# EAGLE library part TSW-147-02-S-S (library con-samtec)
THROUGH-HOLE .025" SQ POST HEADER Source: Samtec TSW.pdf
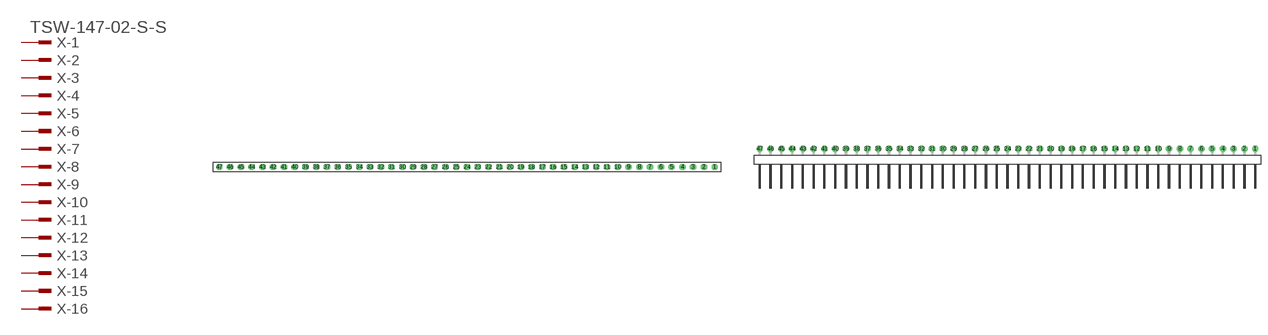
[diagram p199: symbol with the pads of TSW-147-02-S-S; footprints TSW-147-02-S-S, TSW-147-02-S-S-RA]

Designator prefix X; gates -1=MPINV -2=MPIN -3=MPIN -4=MPIN -5=MPIN -6=MPIN -7=MPIN -8=MPIN -9=MPIN -10=MPIN -11=MPIN -12=MPIN -13=MPIN -14=MPIN -15=MPIN -16=MPIN -17=MPIN -18=MPIN -19=MPIN -20=MPIN -21=MPIN -22=MPIN -23=MPIN -24=MPIN -25=MPIN -26=MPIN -27=MPIN -28=MPIN -29=MPIN -30=MPIN -31=MPIN -32=MPIN -33=MPIN -34=MPIN -35=MPIN -36=MPIN -37=MPIN -38=MPIN -39=MPIN -40=MPIN -41=MPIN -42=MPIN -43=MPIN -44=MPIN -45=MPIN -46=MPIN -47=MPIN

## TSW-147-02-S-S (OC_FARNELL: unknown; OC_NEWARK: unknown)  [TSW-147-02-S-S]
1  -1:1  pas
2  -2:1  pas
3  -3:1  pas
4  -4:1  pas
5  -5:1  pas
6  -6:1  pas
7  -7:1  pas
8  -8:1  pas
9  -9:1  pas
10  -10:1  pas
11  -11:1  pas
12  -12:1  pas
13  -13:1  pas
14  -14:1  pas
15  -15:1  pas
16  -16:1  pas
17  -17:1  pas
18  -18:1  pas
19  -19:1  pas
20  -20:1  pas
21  -21:1  pas
22  -22:1  pas
23  -23:1  pas
24  -24:1  pas
25  -25:1  pas
26  -26:1  pas
27  -27:1  pas
28  -28:1  pas
29  -29:1  pas
30  -30:1  pas
31  -31:1  pas
32  -32:1  pas
33  -33:1  pas
34  -34:1  pas
35  -35:1  pas
36  -36:1  pas
37  -37:1  pas
38  -38:1  pas
39  -39:1  pas
40  -40:1  pas
41  -41:1  pas
42  -42:1  pas
43  -43:1  pas
44  -44:1  pas
45  -45:1  pas
46  -46:1  pas
47  -47:1  pas

## TSW-147-02-S-S-RA (OC_FARNELL: unknown; OC_NEWARK: unknown)  [TSW-147-02-S-S-RA]
Pads as for TSW-147-02-S-S

## Footprint TSW-147-02-S-S (pad centres in mm)
THROUGH-HOLE .025" SQ POST HEADER Source: Samtec TSW.pdf
drill 1 pad 1.5 octagon: 1 58.42,0; 2 55.88,0; 3 53.34,0; 4 50.8,0; 5 48.26,0; 6 45.72,0; 7 43.18,0; 8 40.64,0; 9 38.1,0; 10 35.56,0; 11 33.02,0; 12 30.48,0; 13 27.94,0; 14 25.4,0; 15 22.86,0; 16 20.32,0; 17 17.78,0; 18 15.24,0; 19 12.7,0; 20 10.16,0; 21 7.62,0; 22 5.08,0; 23 2.54,0; 24 0,0; 25 -2.54,0; 26 -5.08,0; 27 -7.62,0; 28 -10.16,0; 29 -12.7,0; 30 -15.24,0; 31 -17.78,0; 32 -20.32,0; 33 -22.86,0; 34 -25.4,0; 35 -27.94,0; 36 -30.48,0; 37 -33.02,0; 38 -35.56,0; 39 -38.1,0; 40 -40.64,0; 41 -43.18,0; 42 -45.72,0; 43 -48.26,0; 44 -50.8,0; 45 -53.34,0; 46 -55.88,0; 47 -58.42,0

## Footprint TSW-147-02-S-S-RA (pad centres in mm)
THROUGH-HOLE .025" SQ POST HEADER Source: Samtec TSW.pdf
drill 1 pad 1.5 octagon: 1 58.42,1.524; 2 55.88,1.524; 3 53.34,1.524; 4 50.8,1.524; 5 48.26,1.524; 6 45.72,1.524; 7 43.18,1.524; 8 40.64,1.524; 9 38.1,1.524; 10 35.56,1.524; 11 33.02,1.524; 12 30.48,1.524; 13 27.94,1.524; 14 25.4,1.524; 15 22.86,1.524; 16 20.32,1.524; 17 17.78,1.524; 18 15.24,1.524; 19 12.7,1.524; 20 10.16,1.524; 21 7.62,1.524; 22 5.08,1.524; 23 2.54,1.524; 24 0,1.524; 25 -2.54,1.524; 26 -5.08,1.524; 27 -7.62,1.524; 28 -10.16,1.524; 29 -12.7,1.524; 30 -15.24,1.524; 31 -17.78,1.524; 32 -20.32,1.524; 33 -22.86,1.524; 34 -25.4,1.524; 35 -27.94,1.524; 36 -30.48,1.524; 37 -33.02,1.524; 38 -35.56,1.524; 39 -38.1,1.524; 40 -40.64,1.524; 41 -43.18,1.524; 42 -45.72,1.524; 43 -48.26,1.524; 44 -50.8,1.524; 45 -53.34,1.524; 46 -55.88,1.524; 47 -58.42,1.524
